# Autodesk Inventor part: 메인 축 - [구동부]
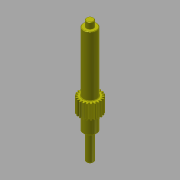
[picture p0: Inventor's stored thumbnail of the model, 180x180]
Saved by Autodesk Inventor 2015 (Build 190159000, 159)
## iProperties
Created: 2016-02
Part Number: 메인 축 - [구동부]
Material: 강철, 연강
Document SubType Name: Modeling
Categories: <?xml version="1.0" encoding="UTF-16"?> <MemberInstance><Categories><FamilyTemplate><FamilyTemplateParameter ValueType="xs:double" Id="1" ObjectReferenceKey="da
Density: 7.86 g/cm^3
Mass: 181.397 g
Surface Area: 79.0018 cm^2
Volume: 23.0784 cm^3
Appearance: 노란색
Author: mdu
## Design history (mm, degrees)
sketch "Sketch1"
  geometry: C1 r 12 at (0, 0)
  constraints: 1 centre point
  dimensions: "d0" = 24 diameter of C1 (= da_da)
extrude "Extrusion1" new body sketch "Sketch1" distance "d1" = 20 (= da_b); taper "d2" = 0 deg
workplane "Work Plane2"
feature "피치 지름" dims "d4" = 10, "d5" = 0
workplane "Work Plane8"
workplane "Work Plane9"
chamfer "모따기1" distance "d49" = 1; stored, may be unused: second distance "d50" = 2, angle "d51" = 45 deg
sketch "스케치3"
  geometry: C1 r 7.5 at (0, 0); 1 further point
  constraints: 1 centre point, 1 coincident
  dimensions: "d52" = 15 diameter of C1
extrude "돌출2" join sketch "스케치3" distance "d53" = 66; taper "d54" = 0 deg
sketch "스케치4"
  geometry: C1 r 4 at (0, 0); 1 further point
  constraints: 1 centre point, 1 coincident
  dimensions: "d55" = 8 diameter of C1
extrude "돌출3" join sketch "스케치4" distance "d56" = 7; taper "d57" = 0 deg
sketch "스케치5"
  geometry: C1 r 7.5 at (0, 0) reference; C2 r 7.5 at (0, 0) reference; 1 further point
extrude "돌출4" join sketch "스케치5" distance "d62" = 16; taper "d63" = 0 deg
sketch "스케치6"
  geometry: C1 r 4 at (0, 0); 1 further point
  constraints: 1 centre point, 1 coincident
  dimensions: "d64" = 8 diameter of C1
extrude "돌출5" join sketch "스케치6" distance "d65" = 30; taper "d66" = 0 deg
chamfer "모따기2" distance "d58" = 0.5; stored, may be unused: second distance "d59" = 2, angle "d60" = 45 deg
fillet "모깎기1" dims "d61" = 0.5
feature "스퍼 기어" dims "da_b" = 20, "da_d" = 22, "da_aw" = 31, "da_da" = 24, "da_df" = 19.5, "da_dw" = 22, angle "da_beta" = 0 deg, "da_lefttooth" = 0, "da_righttooth" = 0
sketch "스케치7" dims "d68" = 18
  geometry: C1 r 0.25 at (0, -9); 2 further points
  constraints: 2 vertical alignment, 1 centre point, 1 coincident, 2 other
  dimensions: "d67" = 0.5 diameter of C1
extrude "돌출6" join sketch "스케치7" distance "d69" = 0.3; taper "d70" = 0 deg
feature "면 이동1"
feature "면 이동2"
feature "면 이동3"
body "Solid1"
sketch "Sketch2"
  geometry: C1 r 12 at (0, 0) reference; C2 r 11 at (0, 0)
  constraints: 1 centre point, 1 coincident
  dimensions: "d3" = 22 diameter of C2 (= da_dw)
body "Srf1"
node "투영된 루프1"
other parameters: "d16" = 31 (= da_aw), "d17" = 0, "d34" = 1.428 (computed from da_z), "d39" = 0, "d41" = 0, "d43" = 31 (= da_aw), "d46" = 31 (= da_aw), "d47" = 0, "d48" = 0
